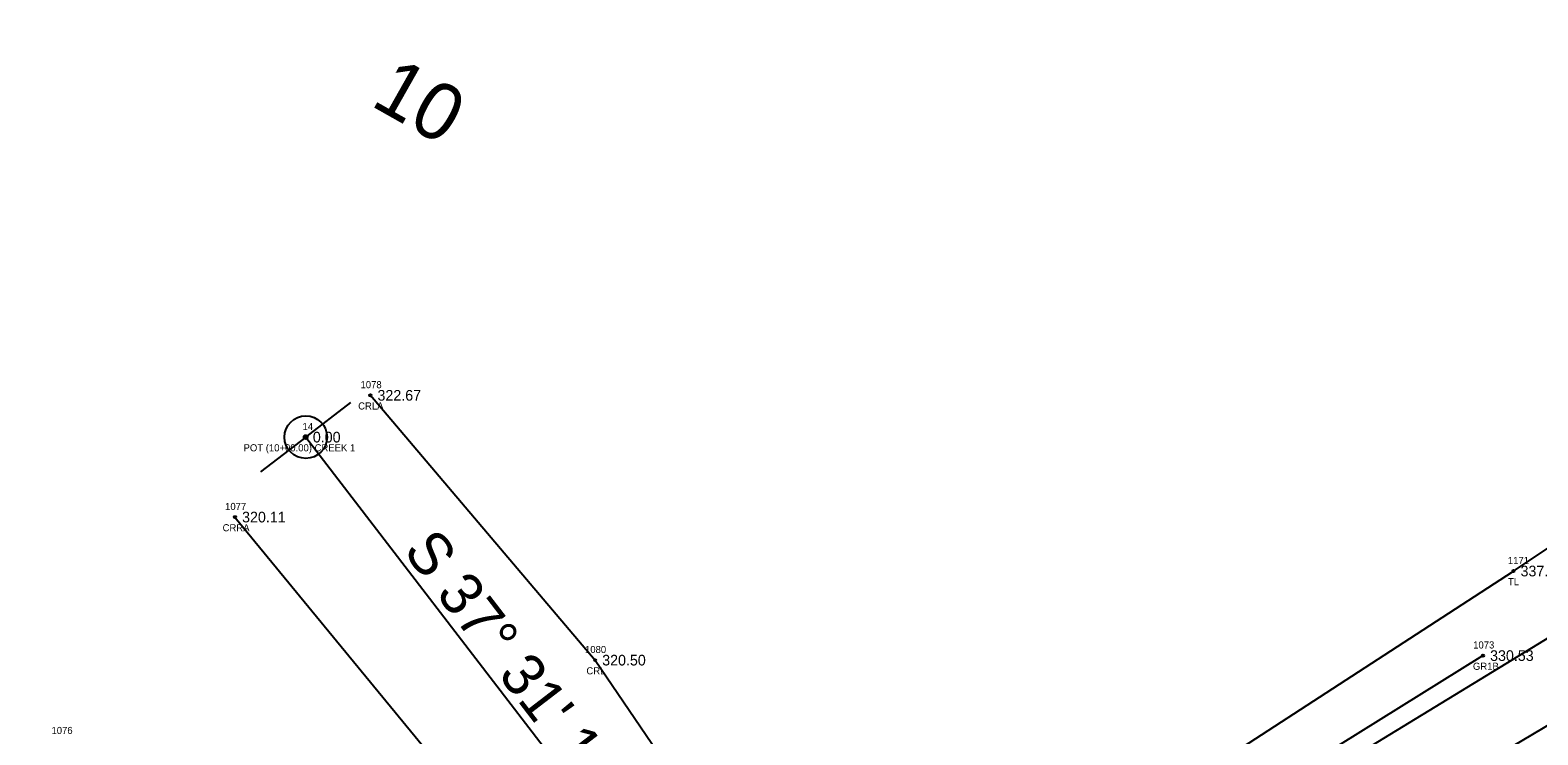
# Model space of a CAD drawing. Extents: x 2231119 to 2232595, y 1035731 to 1037094.
# Drawn here: x 2231465.7 to 2231678, y 1036504.9 to 1036604.1 of the extents above; entities that cross this region are included whole.
import ezdxf

# ---------------------------------------------------------------- set-up
doc = ezdxf.new("R2010")
doc.units = 0
for name, color, linetype in [('RD_EX_GuardRail', 7, 'Continuous'), ('RD_EX_GuardRail_txCode', 7, 'Continuous'), ('RD_EX_H2O', 7, 'Continuous'), ('RD_EX_H2O_txCode', 7, 'Continuous'), ('RD_EX_Road', 7, 'Continuous'), ('RD_EX_TX_GuardRail_ELEV', 7, 'Continuous'), ('RD_EX_TX_H2O_ELEV', 7, 'Continuous'), ('RD_EX_TX_VEG_ELEV', 7, 'Continuous'), ('RD_EX_VEG', 7, 'Continuous'), ('RD_EX_VEG_txCode', 7, 'Continuous'), ('RD_HC_Cl', 7, 'Continuous'), ('RD_HC_Data', 7, 'Continuous'), ('RD_HC_Data_Tic', 7, 'Continuous'), ('RD_HC_Survey_ELEV', 7, 'Continuous'), ('RD_HC_TX_Sta50', 7, 'Continuous'), ('RD_HC_txCode', 7, 'Continuous'), ('RD_SMD_Locator', 7, 'Continuous')]:
    doc.layers.add(name, color=color, linetype=linetype)

msp = doc.modelspace()

# ---------------------------------------------------------------- linework, layer by layer
at = {"layer": 'RD_EX_GuardRail'}
msp.add_lwpolyline([(2231465.75, 1036387.92), (2231495.75, 1036408.95), (2231535.82, 1036434.11), (2231600.8, 1036472.75), (2231670.25, 1036516.04)], dxfattribs=at)
at = {"layer": 'RD_EX_H2O'}
for points in [[(2231513.64, 1036552.7), (2231545.27, 1036515.4), (2231572.49, 1036475.34)], [(2231494.58, 1036535.55), (2231526.23, 1036496.99), (2231544.7, 1036477.47), (2231543.46, 1036469.51)]]:
    msp.add_lwpolyline(points, dxfattribs=at)
at = {"layer": 'RD_EX_Road'}
msp.add_lwpolyline([(2231606.1, 1036462.92), (2231601.27, 1036470.82), (2231681.58, 1036519.84), (2231764.99, 1036568.78), (2231851.5, 1036619.95), (2231935.62, 1036669.65), (2232021.78, 1036720.22), (2232106.75, 1036770.57), (2232190.54, 1036819.2), (2232275.92, 1036870.27)], dxfattribs=at)
at = {"layer": 'RD_EX_VEG'}
msp.add_lwpolyline([(2231598.25, 1036478.35), (2231674.54, 1036527.95), (2231759.25, 1036584.63), (2231839.99, 1036637.88), (2231924.53, 1036692.24), (2232004.98, 1036742.14), (2232090.99, 1036793.16), (2232172.16, 1036843), (2232262.27, 1036890.61)], dxfattribs=at)
at = {"layer": 'RD_HC_Cl'}
for p, q in [((2231548.98, 1036428.87), (2232281.06, 1036863.23)), ((2231504.54, 1036546.81), (2231563.32, 1036470.25))]:
    msp.add_line(p, q, dxfattribs=at)
at = {"layer": 'RD_HC_Data'}
for radius in [3, 0.282]:
    msp.add_circle((2231504.54, 1036546.81), radius, dxfattribs=at)
at = {"layer": 'RD_HC_Data_Tic'}
for q in [(2231510.88, 1036551.68), (2231498.19, 1036541.93)]:
    msp.add_line((2231504.54, 1036546.81), q, dxfattribs=at)
at = {"layer": 'RD_SMD_Locator'}
for centre in [(2231513.64, 1036552.7), (2231504.54, 1036546.81), (2231494.58, 1036535.55), (2231674.54, 1036527.95), (2231545.27, 1036515.4), (2231670.25, 1036516.04)]:
    msp.add_circle(centre, 0.15, dxfattribs=at)

# ---------------------------------------------------------------- texts
at = {"layer": 'RD_EX_GuardRail_txCode'}
for s, p in [('1073', (2231668.87, 1036517.04)), ('GR1B', (2231668.84, 1036514.04))]:
    msp.add_text(s, height=1, dxfattribs=at).set_placement(p)
at = {"layer": 'RD_EX_H2O_txCode'}
for s, p in [('1078', (2231512.25, 1036553.7)), ('CRLA', (2231511.92, 1036550.7)), ('1077', (2231493.19, 1036536.55)), ('CRRA', (2231492.84, 1036533.55)), ('1080', (2231543.85, 1036516.4)), ('CRL', (2231544.05, 1036513.4)), ('1076', (2231468.75, 1036505))]:
    msp.add_text(s, height=1, dxfattribs=at).set_placement(p)
at = {"layer": 'RD_EX_TX_GuardRail_ELEV'}
msp.add_text('330.53', height=1.5, dxfattribs=at).set_placement((2231671.25, 1036515.29))
at = {"layer": 'RD_EX_TX_H2O_ELEV'}
for s, p in [('322.67', (2231514.64, 1036551.95)), ('320.11', (2231495.58, 1036534.8)), ('320.50', (2231546.27, 1036514.65))]:
    msp.add_text(s, height=1.5, dxfattribs=at).set_placement(p)
at = {"layer": 'RD_EX_TX_VEG_ELEV'}
msp.add_text('337.35', height=1.5, dxfattribs=at).set_placement((2231675.54, 1036527.2))
at = {"layer": 'RD_EX_VEG_txCode'}
for s, p in [('1171', (2231673.76, 1036528.95)), ('TL', (2231673.77, 1036525.95))]:
    msp.add_text(s, height=1, dxfattribs=at).set_placement(p)
at = {"layer": 'RD_HC_Data'}
msp.add_text('S 37%%d 31\' 11" E', height=6, rotation=307.5197, dxfattribs=at).set_placement((2231518.13, 1036530.75))
at = {"layer": 'RD_HC_Survey_ELEV'}
msp.add_text('0.00', height=1.5, dxfattribs=at).set_placement((2231505.54, 1036546.06))
at = {"layer": 'RD_HC_TX_Sta50'}
msp.add_text('10', height=8, rotation=330.55, dxfattribs=at).set_placement((2231513.47, 1036593.62))
at = {"layer": 'RD_HC_txCode'}
for s, p in [('14', (2231504.09, 1036547.81)), ('POT (10+00.00) CREEK 1', (2231495.79, 1036544.81))]:
    msp.add_text(s, height=1, dxfattribs=at).set_placement(p)

doc.saveas('drawing.dxf')
